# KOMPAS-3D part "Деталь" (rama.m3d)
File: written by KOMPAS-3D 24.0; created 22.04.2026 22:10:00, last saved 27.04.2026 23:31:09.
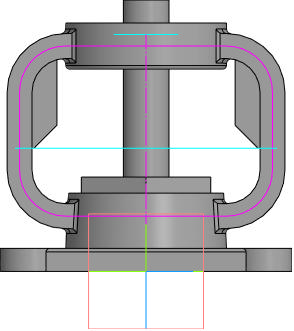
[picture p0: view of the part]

Document properties: Автор: mrdid; Полное имя файла: C:\Работа\ГОТОВЫЕ ИСХОДНИКИ\VSO2130M-F-S Клапан запорный сальниковый DN.ru Ду15-100 Ру40\исходные материалы\DN65\rama.m3d

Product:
- Part/product: Деталь
    Масса: 3.382904

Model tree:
1. Эскиз:2  (with: Ребро.Элемент выдавливания:14)
2. Элемент выдавливания:1
     Расстояние 1 = 10
3. Эскиз:3  (with: Грань.Элемент выдавливания:1, Ребро.Элемент выдавливания:1)
4. Элемент выдавливания:2
     Расстояние 2 = 10
5. Эскиз:4  (with: Грань.Элемент выдавливания:1)
6. Элемент выдавливания:3
     Угол 1 = -3
7. Эскиз:5  (with: Грань.Элемент выдавливания:3, Ребро.Элемент выдавливания:3)
8. Элемент выдавливания:4
9. Эскиз:23  (with: Грань.Элемент выдавливания:4, Ребро.Элемент выдавливания:4)
10. Элемент выдавливания:21  (labels: Деталь2; Грань.Твердое тело1)
     Расстояние 1 = 76.9137
11. Эскиз:7  (with: Грань.Элемент выдавливания:4, Ребро.Элемент выдавливания:3)
12. Элемент выдавливания:6  (with: Грань.Элемент выдавливания:3)
     Расстояние 2 = 7
13. Смещенная плоскость:4  (labels: Деталь2; Грань.Твердое тело1)
     Расстояние = 15
14. Эскиз:24  (with: Ребро.Элемент выдавливания:3)
15. Элемент выдавливания:22
     Расстояние 1 = 5; Расстояние 2 = 15
16. Эскиз:25  (with: Ребро.Элемент выдавливания:3)
17. Эскиз:26  (with: Ребро.Элемент выдавливания:3)
18. Элемент по траектории:1
     Длина траектории = 333.491
19. Скругление:8  (with: Ребро.Элемент по траектории:1)
     Радиус = 2
20. Скругление:9  (with: Ребро.Элемент по траектории:1)
     Радиус = 2
21. Смещенная плоскость:5  (with: Грань.Элемент выдавливания:1)
22. Эскиз:27  (with: Вершина.Элемент по траектории:1)
23. Элемент выдавливания:23  (with: Грань.Элемент выдавливания:22)
     Расстояние 1 = 39.4137; Смещение 1 = 5
24. Скругление:1  (with: Ребро.Элемент выдавливания:1)
     Радиус = 1.5
25. Скругление:10  (with: Ребро.Элемент выдавливания:22)
     Радиус = 1.5
26. Фаска:1  (with: Ребро.Элемент выдавливания:23)
     Угол = 45; Длина 1 = 10; Длина 2 = 10
27. Массив по концентрической сетке:1  (with: Элемент выдавливания:2, Эскиз:3)  (labels: Клапан запорный DN.ru Ду65 Ру40)  (4 pattern instances)
     Шаг 2 = 360

Expressions: DN/2; DN/4; DN/6; H/4-10
Referenced files in C:\Работа\ГОТОВЫЕ ИСХОДНИКИ\VSO2130M-F-S Клапан запорный сальниковый DN.ru Ду15-100 Ру40\исходные материалы\DN65\: VSO2130M-F-S Клапан запорный DN.ru Ду65 Ру40.a3d
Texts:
  DN+5
  Ось Y.Начало координат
